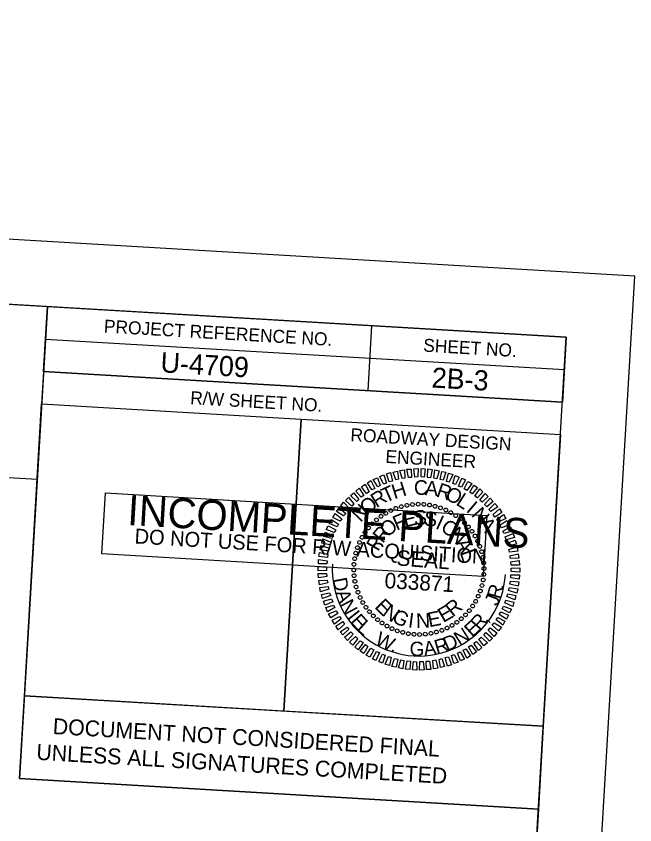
# Model space of a CAD drawing. Extents: x 2011701 to 2013463, y 444552 to 445750.
# Drawn here: x 2013225 to 2013463.2, y 445439.1 to 445750.4 of the extents above; entities that cross this region are included whole.
import ezdxf

# ---------------------------------------------------------------- set-up
doc = ezdxf.new("R2010")
doc.units = 0
for name, color, linetype in [('Old_Level_58', 7, 'Continuous'), ('Scratch_Level_0', 7, 'Continuous'), ('Sheet Clip Boundary CELL', 7, 'Continuous'), ('Sheet Data Field CELL', 7, 'Continuous'), ('Sheet Plan And Profile CELL', 7, 'Continuous'), ('Sheet Plot Border Outside CELL', 7, 'Continuous'), ('Sheet Professional Seal CELL', 7, 'Continuous'), ('Sheet Profile Grid Minor CELL', 7, 'Continuous'), ('Sheet Sticker Exception Certification CELL', 7, 'Continuous'), ('Sheet Sticker Incomplete CELL', 7, 'Continuous')]:
    doc.layers.add(name, color=color, linetype=linetype)

msp = doc.modelspace()

# ---------------------------------------------------------------- linework, layer by layer
at = {"layer": 'Old_Level_58'}
msp.add_lwpolyline([(2013037.32, 445650.4), (2013237.02, 445638.63), (2013233.1, 445572.05), (2013033.4, 445583.82)], close=True, dxfattribs=at)
at = {"layer": 'Scratch_Level_0'}
msp.add_arc((2013380.03, 445537.48), 33.36, 176.6264, 356.6264, dxfattribs=at)
at = {"layer": 'Sheet Clip Boundary CELL'}
msp.add_lwpolyline([(2011939.33, 445715.12), (2013237.02, 445638.63), (2013226.31, 445456.93), (2013426.02, 445445.16), (2013374.94, 444578.67), (2011877.54, 444666.94)], close=True, dxfattribs=at)
at = {"layer": 'Sheet Plan And Profile CELL'}
for p, q in [((2013361.85, 445631.22), (2013360.38, 445606.26)), ((2013236.29, 445626.1), (2013435.99, 445614.33)), ((2013235.55, 445613.62), (2013234.81, 445601.14)), ((2013235.55, 445613.62), (2013435.25, 445601.85)), ((2013334.69, 445595.25), (2013328.07, 445483))]:
    msp.add_line(p, q, dxfattribs=at)
for points in [[(2013436.73, 445626.85), (2011939.33, 445715.12), (2011877.54, 444666.94), (2013374.94, 444578.67)], [(2013237.02, 445638.63), (2013436.73, 445626.85), (2013435.25, 445601.85), (2013235.55, 445613.62)], [(2013234.81, 445601.14), (2013334.69, 445595.25), (2013328.07, 445482.95), (2013228.19, 445488.84)], [(2013334.69, 445595.25), (2013434.52, 445589.37), (2013427.9, 445477.06), (2013328.07, 445482.95)]]:
    msp.add_lwpolyline(points, close=True, dxfattribs=at)
at = {"layer": 'Sheet Plot Border Outside CELL'}
msp.add_lwpolyline([(2011701.37, 444652.28), (2013398.42, 444552.25), (2013463.16, 445650.34), (2011766.1, 445750.38)], close=True, dxfattribs=at)
at = {"layer": 'Sheet Professional Seal CELL'}
for p, q in [((2013369.19, 445560.11), (2013369.19, 445560.11)), ((2013371.2, 445561), (2013371.2, 445561)), ((2013373.24, 445561.68), (2013373.24, 445561.68)), ((2013375.38, 445562.15), (2013375.38, 445562.15)), ((2013377.59, 445562.42), (2013377.59, 445562.42)), ((2013379.76, 445562.59), (2013379.76, 445562.59)), ((2013381.96, 445562.51), (2013381.96, 445562.51)), ((2013384.15, 445562.24), (2013384.15, 445562.24)), ((2013386.27, 445561.76), (2013386.27, 445561.76)), ((2013388.34, 445561.19), (2013388.34, 445561.19)), ((2013390.4, 445560.36), (2013390.4, 445560.36)), ((2013363.67, 445556.53), (2013363.67, 445556.53)), ((2013365.41, 445557.93), (2013365.41, 445557.93)), ((2013367.23, 445559.08), (2013367.23, 445559.08)), ((2013392.34, 445559.35), (2013392.34, 445559.35)), ((2013394.23, 445558.24), (2013394.23, 445558.24)), ((2013395.95, 445556.88), (2013395.95, 445556.88)), ((2013360.63, 445553.4), (2013360.63, 445553.4)), ((2013362.09, 445555.07), (2013362.09, 445555.07)), ((2013397.62, 445555.43), (2013397.62, 445555.43)), ((2013399.08, 445553.84), (2013399.08, 445553.84)), ((2013359.28, 445551.68), (2013359.28, 445551.68)), ((2013400.48, 445552.11), (2013400.48, 445552.11)), ((2013401.62, 445550.29), (2013401.62, 445550.29)), ((2013357.15, 445547.85), (2013357.15, 445547.85)), ((2013358.17, 445549.79), (2013358.17, 445549.79)), ((2013402.66, 445548.32), (2013402.66, 445548.32)), ((2013356.33, 445545.79), (2013356.33, 445545.79)), ((2013403.54, 445546.32), (2013403.54, 445546.32)), ((2013404.22, 445544.27), (2013404.22, 445544.27)), ((2013355.28, 445541.6), (2013355.28, 445541.6)), ((2013355.76, 445543.72), (2013355.76, 445543.72)), ((2013404.7, 445542.14), (2013404.7, 445542.14)), ((2013355, 445539.41), (2013355, 445539.41)), ((2013404.97, 445539.92), (2013404.97, 445539.92)), ((2013405.14, 445537.76), (2013405.14, 445537.76)), ((2013354.92, 445537.21), (2013354.92, 445537.21)), ((2013355.1, 445535.05), (2013355.1, 445535.05)), ((2013380.03, 445537.48), (2013380.03, 445537.48)), ((2013405.06, 445535.56), (2013405.06, 445535.56)), ((2013355.36, 445532.83), (2013355.36, 445532.83)), ((2013404.78, 445533.37), (2013404.78, 445533.37)), ((2013355.84, 445530.7), (2013355.84, 445530.7)), ((2013356.52, 445528.65), (2013356.52, 445528.65)), ((2013403.73, 445529.18), (2013403.73, 445529.18)), ((2013404.31, 445531.25), (2013404.31, 445531.25)), ((2013357.4, 445526.65), (2013357.4, 445526.65)), ((2013402.91, 445527.12), (2013402.91, 445527.12)), ((2013358.44, 445524.68), (2013358.44, 445524.68)), ((2013359.59, 445522.86), (2013359.59, 445522.86)), ((2013400.78, 445523.29), (2013400.78, 445523.29)), ((2013401.9, 445525.18), (2013401.9, 445525.18)), ((2013360.99, 445521.13), (2013360.99, 445521.13)), ((2013362.45, 445519.54), (2013362.45, 445519.54)), ((2013397.98, 445519.9), (2013397.98, 445519.9)), ((2013399.43, 445521.57), (2013399.43, 445521.57)), ((2013364.11, 445518.09), (2013364.11, 445518.09)), ((2013365.84, 445516.73), (2013365.84, 445516.73)), ((2013394.65, 445517.04), (2013394.65, 445517.04)), ((2013396.39, 445518.44), (2013396.39, 445518.44)), ((2013367.72, 445515.62), (2013367.72, 445515.62)), ((2013369.67, 445514.61), (2013369.67, 445514.61)), ((2013371.72, 445513.78), (2013371.72, 445513.78)), ((2013373.79, 445513.21), (2013373.79, 445513.21)), ((2013384.69, 445512.82), (2013384.69, 445512.82)), ((2013386.82, 445513.29), (2013386.82, 445513.29)), ((2013388.86, 445513.97), (2013388.86, 445513.97)), ((2013390.87, 445514.86), (2013390.87, 445514.86)), ((2013392.83, 445515.89), (2013392.83, 445515.89)), ((2013375.92, 445512.73), (2013375.92, 445512.73)), ((2013378.11, 445512.45), (2013378.11, 445512.45)), ((2013380.3, 445512.38), (2013380.3, 445512.38)), ((2013382.47, 445512.55), (2013382.47, 445512.55))]:
    msp.add_line(p, q, dxfattribs=at)
for points in [[(2013371.14, 445571.87), (2013370.17, 445574.93), (2013371.74, 445575.29), (2013372.21, 445572.16)], [(2013373.57, 445572.38), (2013372.71, 445575.58), (2013374.43, 445575.83), (2013374.64, 445572.56)], [(2013376, 445572.78), (2013375.39, 445576.02), (2013377.05, 445576.08), (2013377.21, 445572.86)], [(2013378.42, 445572.94), (2013378.05, 445576.17), (2013379.76, 445576.27), (2013379.62, 445573.02)], [(2013380.93, 445573.04), (2013380.87, 445576.3), (2013382.51, 445576.16), (2013382.12, 445572.92)], [(2013383.32, 445572.85), (2013383.51, 445576.1), (2013385.15, 445575.95), (2013384.51, 445572.73)], [(2013385.81, 445572.56), (2013386.2, 445575.79), (2013387.83, 445575.39), (2013386.99, 445572.29)], [(2013388.18, 445572.02), (2013388.82, 445575.18), (2013390.45, 445574.84), (2013389.37, 445571.79)], [(2013364.17, 445569.22), (2013362.48, 445572.03), (2013364.08, 445572.73), (2013365.16, 445569.77)], [(2013366.39, 445570.29), (2013364.96, 445573.18), (2013366.54, 445573.79), (2013367.51, 445570.68)], [(2013368.65, 445571.21), (2013367.52, 445574.18), (2013369.05, 445574.7), (2013369.91, 445571.44)], [(2013390.69, 445571.32), (2013391.38, 445574.53), (2013393.05, 445574.03), (2013391.72, 445571)], [(2013393.05, 445570.53), (2013393.98, 445573.58), (2013395.5, 445572.99), (2013394.08, 445570.11)], [(2013395.24, 445569.5), (2013396.58, 445572.57), (2013397.94, 445571.89), (2013396.37, 445569.08)], [(2013359.92, 445566.72), (2013357.91, 445569.24), (2013359.32, 445570.21), (2013360.9, 445567.31)], [(2013361.9, 445568.1), (2013360.21, 445570.76), (2013361.56, 445571.63), (2013363.04, 445568.64)], [(2013397.43, 445568.41), (2013398.85, 445571.29), (2013400.36, 445570.5), (2013398.5, 445567.8)], [(2013399.66, 445567.13), (2013401.18, 445569.9), (2013402.62, 445568.96), (2013400.57, 445566.48)], [(2013356.08, 445563.64), (2013353.65, 445565.84), (2013354.97, 445566.91), (2013356.93, 445564.39)], [(2013357.83, 445565.29), (2013355.76, 445567.62), (2013357.03, 445568.74), (2013358.82, 445565.93)], [(2013401.53, 445565.67), (2013403.45, 445568.46), (2013404.68, 445567.34), (2013402.59, 445565.01)], [(2013403.49, 445564.05), (2013405.49, 445566.69), (2013406.73, 445565.51), (2013404.39, 445563.3)], [(2013352.61, 445560.04), (2013350.02, 445561.89), (2013351.05, 445563.29), (2013353.32, 445560.95)], [(2013354.22, 445561.85), (2013351.74, 445563.95), (2013352.91, 445565.18), (2013354.97, 445562.7)], [(2013405.29, 445562.39), (2013407.49, 445564.87), (2013408.62, 445563.6), (2013406.2, 445561.59)], [(2013406.99, 445560.54), (2013409.27, 445562.76), (2013410.4, 445561.49), (2013407.69, 445559.7)], [(2013351, 445558.13), (2013348.29, 445559.79), (2013349.37, 445561.13), (2013351.85, 445558.98)], [(2013408.63, 445558.64), (2013411.05, 445560.75), (2013412.02, 445559.34), (2013409.27, 445557.6)], [(2013348.54, 445553.82), (2013345.51, 445555.15), (2013346.35, 445556.65), (2013349.1, 445554.89)], [(2013349.67, 445556.05), (2013346.9, 445557.47), (2013347.74, 445558.97), (2013350.33, 445556.97)], [(2013410.01, 445556.6), (2013412.58, 445558.56), (2013413.44, 445557.05), (2013410.55, 445555.62)], [(2013347.41, 445551.68), (2013344.37, 445552.76), (2013345.11, 445554.27), (2013348.02, 445552.69)], [(2013411.19, 445554.48), (2013413.94, 445556.22), (2013414.8, 445554.67), (2013411.83, 445553.44)], [(2013412.35, 445552.21), (2013415.25, 445553.79), (2013415.81, 445552.2), (2013412.9, 445551.22)], [(2013346.52, 445549.33), (2013343.46, 445550.16), (2013343.91, 445551.79), (2013346.98, 445550.35)], [(2013413.23, 445550), (2013416.26, 445551.33), (2013416.81, 445549.69), (2013413.66, 445548.88)], [(2013345.73, 445546.97), (2013342.66, 445547.55), (2013343.11, 445549.23), (2013346.19, 445547.99)], [(2013413.99, 445547.6), (2013417.11, 445548.72), (2013417.57, 445547.14), (2013414.42, 445546.53)], [(2013344.79, 445542.07), (2013341.55, 445542.36), (2013341.75, 445544), (2013344.96, 445543.26)], [(2013345.18, 445544.45), (2013342, 445544.94), (2013342.3, 445546.62), (2013345.5, 445545.63)], [(2013414.64, 445545.16), (2013417.91, 445546.12), (2013418.11, 445544.46), (2013414.93, 445544.09)], [(2013344.59, 445539.57), (2013341.34, 445539.62), (2013341.44, 445541.31), (2013344.66, 445540.77)], [(2013415.1, 445542.73), (2013418.3, 445543.49), (2013418.5, 445541.78), (2013415.34, 445541.66)], [(2013415.41, 445540.31), (2013418.69, 445540.82), (2013418.74, 445539.11), (2013415.54, 445539.1)], [(2013344.5, 445537.08), (2013341.23, 445536.87), (2013341.23, 445538.57), (2013344.47, 445538.28)], [(2013415.57, 445537.89), (2013418.84, 445538.1), (2013418.84, 445536.4), (2013415.6, 445536.69)], [(2013344.65, 445534.66), (2013341.37, 445534.15), (2013341.32, 445535.86), (2013344.53, 445535.87)], [(2013415.47, 445535.4), (2013418.72, 445535.35), (2013418.62, 445533.66), (2013415.4, 445534.2)], [(2013344.96, 445532.24), (2013341.76, 445531.48), (2013341.56, 445533.19), (2013344.72, 445533.31)], [(2013415.27, 445532.9), (2013418.51, 445532.61), (2013418.31, 445530.97), (2013415.1, 445531.71)], [(2013345.42, 445529.81), (2013342.16, 445528.85), (2013341.96, 445530.51), (2013345.13, 445530.88)], [(2013346.08, 445527.37), (2013342.96, 445526.25), (2013342.5, 445527.83), (2013345.64, 445528.44)], [(2013414.88, 445530.52), (2013418.06, 445530.03), (2013417.76, 445528.35), (2013414.56, 445529.34)], [(2013346.84, 445524.97), (2013343.8, 445523.64), (2013343.25, 445525.28), (2013346.4, 445526.09)], [(2013413.54, 445525.64), (2013416.6, 445524.81), (2013416.15, 445523.18), (2013413.08, 445524.62)], [(2013414.33, 445528), (2013417.4, 445527.42), (2013416.95, 445525.74), (2013413.87, 445526.98)], [(2013347.71, 445522.76), (2013344.81, 445521.18), (2013344.25, 445522.76), (2013347.17, 445523.75)], [(2013412.65, 445523.29), (2013415.69, 445522.21), (2013414.95, 445520.7), (2013412.04, 445522.27)], [(2013348.88, 445520.49), (2013346.12, 445518.75), (2013345.26, 445520.3), (2013348.24, 445521.53)], [(2013350.05, 445518.37), (2013347.49, 445516.41), (2013346.62, 445517.92), (2013349.51, 445519.35)], [(2013411.53, 445521.15), (2013414.55, 445519.82), (2013413.71, 445518.32), (2013410.96, 445520.08)], [(2013351.44, 445516.33), (2013349.01, 445514.22), (2013348.04, 445515.63), (2013350.8, 445517.37)], [(2013409.07, 445516.84), (2013411.77, 445515.18), (2013410.69, 445513.84), (2013408.22, 445515.99)], [(2013410.39, 445518.92), (2013413.16, 445517.5), (2013412.32, 445516), (2013409.74, 445518)], [(2013353.08, 445514.43), (2013350.79, 445512.21), (2013349.67, 445513.48), (2013352.38, 445515.27)], [(2013354.77, 445512.58), (2013352.57, 445510.1), (2013351.45, 445511.37), (2013353.87, 445513.38)], [(2013405.84, 445513.12), (2013408.32, 445511.02), (2013407.15, 445509.79), (2013405.09, 445512.27)], [(2013407.45, 445514.93), (2013410.05, 445513.08), (2013409.01, 445511.68), (2013406.75, 445514.02)], [(2013356.58, 445510.92), (2013354.57, 445508.28), (2013353.34, 445509.46), (2013355.67, 445511.67)], [(2013358.54, 445509.3), (2013356.62, 445506.51), (2013355.38, 445507.63), (2013357.47, 445509.96)], [(2013403.98, 445511.33), (2013406.41, 445509.13), (2013405.09, 445508.06), (2013403.14, 445510.58)], [(2013360.4, 445507.84), (2013358.89, 445505.07), (2013357.44, 445506.01), (2013359.49, 445508.49)], [(2013362.63, 445506.56), (2013361.21, 445503.68), (2013359.7, 445504.47), (2013361.57, 445507.17)], [(2013398.16, 445506.86), (2013399.86, 445504.21), (2013398.5, 445503.34), (2013397.03, 445506.33)], [(2013400.15, 445508.25), (2013402.15, 445505.73), (2013400.74, 445504.76), (2013399.16, 445507.66)], [(2013402.23, 445509.68), (2013404.3, 445507.35), (2013403.03, 445506.23), (2013401.24, 445509.04)], [(2013364.82, 445505.47), (2013363.49, 445502.4), (2013362.13, 445503.08), (2013363.69, 445505.89)], [(2013367.01, 445504.44), (2013366.08, 445501.39), (2013364.57, 445501.98), (2013365.99, 445504.85)], [(2013369.37, 445503.65), (2013368.68, 445500.44), (2013367.01, 445500.94), (2013368.34, 445503.96)], [(2013391.42, 445503.76), (2013392.54, 445500.78), (2013391.01, 445500.27), (2013390.15, 445503.53)], [(2013393.67, 445504.68), (2013395.11, 445501.79), (2013393.52, 445501.18), (2013392.55, 445504.29)], [(2013395.89, 445505.75), (2013397.58, 445502.94), (2013395.99, 445502.23), (2013394.91, 445505.2)], [(2013371.89, 445502.95), (2013371.25, 445499.79), (2013369.62, 445500.13), (2013370.7, 445503.17)], [(2013374.26, 445502.41), (2013373.87, 445499.18), (2013372.24, 445499.58), (2013373.07, 445502.68)], [(2013376.74, 445502.12), (2013376.55, 445498.87), (2013374.91, 445499.02), (2013375.55, 445502.24)], [(2013379.14, 445501.93), (2013379.2, 445498.67), (2013377.55, 445498.81), (2013377.94, 445502.05)], [(2013381.65, 445502.03), (2013382.01, 445498.8), (2013380.3, 445498.7), (2013380.44, 445501.95)], [(2013384.06, 445502.19), (2013384.67, 445498.94), (2013383.02, 445498.89), (2013382.85, 445502.11)], [(2013386.49, 445502.59), (2013387.35, 445499.39), (2013385.63, 445499.14), (2013385.43, 445502.41)], [(2013388.92, 445503.1), (2013389.9, 445500.04), (2013388.32, 445499.68), (2013387.86, 445502.81)]]:
    msp.add_lwpolyline(points, close=True, dxfattribs=at)
for centre, major_axis in [((2013375.41, 445562.13), (-0.133, 0.708)), ((2013377.57, 445562.44), (-0.071, 0.717)), ((2013379.76, 445562.56), (-0.008, 0.72)), ((2013381.94, 445562.49), (0.055, 0.718)), ((2013384.12, 445562.23), (0.117, 0.71)), ((2013367.26, 445559.07), (-0.367, 0.62)), ((2013369.18, 445560.1), (-0.311, 0.649)), ((2013371.2, 445560.96), (-0.254, 0.674)), ((2013373.28, 445561.64), (-0.194, 0.693)), ((2013386.26, 445561.78), (0.179, 0.697)), ((2013388.35, 445561.14), (0.239, 0.679)), ((2013390.38, 445560.33), (0.297, 0.656)), ((2013392.33, 445559.34), (0.353, 0.627)), ((2013363.7, 445556.52), (-0.469, 0.546)), ((2013365.42, 445557.87), (-0.419, 0.585)), ((2013394.19, 445558.19), (0.407, 0.594)), ((2013395.94, 445556.87), (0.457, 0.557)), ((2013360.64, 445553.39), (-0.557, 0.457)), ((2013362.1, 445555.02), (-0.515, 0.504)), ((2013397.57, 445555.41), (0.504, 0.515)), ((2013399.07, 445553.82), (0.546, 0.469)), ((2013358.18, 445549.79), (-0.627, 0.353)), ((2013359.33, 445551.64), (-0.594, 0.407)), ((2013400.42, 445552.09), (0.585, 0.419)), ((2013401.61, 445550.26), (0.62, 0.367)), ((2013357.19, 445547.83), (-0.656, 0.297)), ((2013402.64, 445548.33), (0.649, 0.311)), ((2013403.5, 445546.32), (0.674, 0.254)), ((2013355.74, 445543.71), (-0.697, 0.179)), ((2013356.37, 445545.8), (-0.679, 0.239)), ((2013404.18, 445544.24), (0.693, 0.194)), ((2013355.29, 445541.57), (-0.71, 0.117)), ((2013404.68, 445542.11), (0.708, 0.133)), ((2013354.95, 445537.21), (-0.72, -0.008)), ((2013355.02, 445539.4), (-0.718, 0.055)), ((2013404.99, 445539.94), (0.717, 0.071)), ((2013405.11, 445537.76), (0.72, 0.008)), ((2013355.07, 445535.03), (-0.717, -0.071)), ((2013405.04, 445535.57), (0.718, -0.055)), ((2013355.38, 445532.86), (-0.708, -0.133)), ((2013355.88, 445530.73), (-0.693, -0.194)), ((2013404.33, 445531.26), (0.697, -0.179)), ((2013404.78, 445533.4), (0.71, -0.117)), ((2013356.56, 445528.65), (-0.674, -0.254)), ((2013403.69, 445529.17), (0.679, -0.239)), ((2013357.42, 445526.64), (-0.649, -0.311)), ((2013358.45, 445524.71), (-0.62, -0.367)), ((2013401.89, 445525.18), (0.627, -0.353)), ((2013402.88, 445527.13), (0.656, -0.297)), ((2013359.65, 445522.88), (-0.585, -0.419)), ((2013399.42, 445521.57), (0.557, -0.457)), ((2013400.73, 445523.33), (0.594, -0.407)), ((2013361, 445521.15), (-0.546, -0.469)), ((2013362.49, 445519.56), (-0.504, -0.515)), ((2013396.36, 445518.45), (0.469, -0.546)), ((2013397.96, 445519.95), (0.515, -0.504)), ((2013364.12, 445518.1), (-0.457, -0.557)), ((2013365.87, 445516.78), (-0.407, -0.594)), ((2013367.73, 445515.63), (-0.353, -0.627)), ((2013392.81, 445515.9), (0.367, -0.62)), ((2013394.64, 445517.1), (0.419, -0.585)), ((2013369.68, 445514.64), (-0.297, -0.656)), ((2013371.71, 445513.82), (-0.239, -0.679)), ((2013373.81, 445513.19), (-0.179, -0.697)), ((2013375.95, 445512.74), (-0.117, -0.71)), ((2013378.12, 445512.48), (-0.055, -0.718)), ((2013380.31, 445512.41), (0.008, -0.72)), ((2013382.49, 445512.53), (0.071, -0.717)), ((2013384.66, 445512.83), (0.133, -0.708)), ((2013386.79, 445513.33), (0.194, -0.693)), ((2013388.87, 445514.01), (0.254, -0.674)), ((2013390.88, 445514.87), (0.311, -0.649))]:
    msp.add_ellipse(centre, major_axis=major_axis, ratio=0.999708, dxfattribs=at)
at = {"layer": 'Sheet Sticker Exception Certification CELL'}
for p, q in [((2013226.31, 445456.93), (2013228.2, 445488.85)), ((2013228.2, 445488.85), (2013427.9, 445477.08)), ((2013427.9, 445477.06), (2013426.02, 445445.14)), ((2013426.02, 445445.16), (2013226.31, 445456.93))]:
    msp.add_line(p, q, dxfattribs=at)
at = {"layer": 'Sheet Sticker Incomplete CELL'}
msp.add_lwpolyline([(2013258.01, 445543.43), (2013259.39, 445566.89), (2013406.14, 445558.23), (2013404.75, 445534.78)], close=True, dxfattribs=at)

# ---------------------------------------------------------------- texts
at = {"layer": 'Sheet Data Field CELL'}
for s, p in [('U-4709', (2013280.41, 445613.33)), ('2B-3', (2013384.79, 445607.48))]:
    msp.add_text(s, height=7.75, rotation=356.6264, dxfattribs=at).set_placement(p)
at = {"layer": 'Sheet Plan And Profile CELL'}
for s, height, p in [('PROJECT REFERENCE NO.', 5.0001, (2013258.67, 445628.63)), ('SHEET NO.', 5, (2013381.6, 445621.29)), ('R/W SHEET NO.', 5.0001, (2013291.91, 445601.08)), ('ROADWAY DESIGN', 5.0001, (2013353.56, 445586.83)), ('ENGINEER', 5, (2013367.04, 445578.47))]:
    msp.add_text(s, height=height, rotation=356.6264, dxfattribs=at).set_placement(p)
at = {"layer": 'Sheet Professional Seal CELL'}
for s, height, rotation, p in [('T', 5.64, 24.4462, (2013367.21, 445562.98)), ('H', 5.64, 17.2459, (2013370.55, 445564.44)), ('C', 5.64, 2.8463, (2013378.26, 445565.99)), ('A', 5.64, 355.6467, (2013382.22, 445566.06)), ('R', 5.64, 341.2475, (2013386.4, 445565.61)), ('O', 5.64, 334.0476, (2013389.7, 445564.66)), ('R', 5.64, 31.6469, (2013363.69, 445560.99)), ('L', 5.64, 326.8473, (2013393.98, 445562.56)), ('N', 5.64, 46.0499, (2013357.59, 445555.34)), ('O', 5.64, 38.8482, (2013360.06, 445558.1)), ('I', 5.64, 319.6466, (2013397.88, 445559.92)), ('E', 5.64, 13.2375, (2013374.72, 445553.63)), ('S', 5.64, 3.882, (2013378.23, 445554.47)), ('S', 5.64, 354.5268, (2013381.82, 445554.31)), ('N', 5.64, 312.4453, (2013399.94, 445558.25)), ('O', 5.64, 41.3077, (2013367.97, 445549.57)), ('F', 5.64, 22.5935, (2013371.44, 445552.32)), ('I', 5.64, 335.816, (2013386.08, 445553.36)), ('A', 5.64, 305.2436, (2013402.71, 445555.13)), ('R', 5.64, 50.6661, (2013366.08, 445547.22)), ('O', 5.64, 326.4599, (2013388.03, 445552.54)), ('N', 5.64, 317.103, (2013391.26, 445550.35)), ('P', 5.64, 60.0253, (2013364.3, 445544.12)), ('A', 5.64, 298.3867, (2013393.95, 445547.58)), ('SEAL', 5.998, 355.6264, (2013371.26, 445539)), ('L', 5.64, 289.0273, (2013395.69, 445544.02)), ('E', 5.64, 314.9033, (2013362.74, 445522.83)), ('R', 5.64, 39.1078, (2013393.06, 445518.94)), ('N', 5.64, 324.2604, (2013365.58, 445519.96)), ('E', 5.64, 29.7505, (2013389.38, 445516.8)), ('G', 5.64, 333.6167, (2013369.24, 445517.49)), ('I', 5.64, 352.3276, (2013375.66, 445515.2)), ('N', 5.64, 1.6828, (2013379, 445514.86)), ('E', 5.64, 11.0382, (2013383.98, 445515.16))]:
    msp.add_text(s, height=height, rotation=rotation, dxfattribs=at).set_placement(p)
at = {"layer": 'Sheet Profile Grid Minor CELL'}
for s, height, rotation, p in [('033871', 5.998, 356.6264, (2013366.68, 445530.25)), ('D', 5.5, 280.8946, (2013346.77, 445533.79)), ('R', 5.5, 73.9805, (2013411.37, 445525.72)), ('A', 5.5, 290.0393, (2013347.78, 445528.55)), ('.', 5.5, 80.9069, (2013412.56, 445529.58)), ('N', 5.5, 298.2251, (2013349.38, 445524.05)), ('J', 5.5, 69.1119, (2013410.25, 445523.1)), ('I', 5.5, 308.1568, (2013352.15, 445518.97)), ('E', 5.5, 311.6772, (2013353.34, 445517.29)), ('R', 5.5, 49.0052, (2013403.47, 445513.59)), ('L', 5.5, 318.2602, (2013355.83, 445514.36)), ('E', 5.5, 42.4222, (2013400.57, 445511.06)), (',', 5.5, 55.9317, (2013406.18, 445516.59)), ('W', 5.5, 333.5156, (2013362.77, 445508.81)), ('N', 5.5, 32.4905, (2013395.71, 445507.91)), ('G', 5.5, 358.3019, (2013376.38, 445504.21)), ('A', 5.5, 8.2337, (2013382.17, 445504.08)), ('R', 5.5, 16.4194, (2013386.91, 445504.73)), ('D', 5.5, 23.3459, (2013390.81, 445505.8)), ('.', 5.5, 345.1217, (2013368.89, 445505.92))]:
    msp.add_text(s, height=height, rotation=rotation, dxfattribs=at).set_placement(p)
at = {"layer": 'Sheet Sticker Exception Certification CELL'}
for s, p in [('DOCUMENT NOT CONSIDERED FINAL', (2013238.97, 445474.11)), ('UNLESS ALL SIGNATURES COMPLETED', (2013232.65, 445464.21))]:
    msp.add_text(s, height=6.124, rotation=356.6264, dxfattribs=at).set_placement(p)
at = {"layer": 'Sheet Sticker Incomplete CELL'}
for s, height, p in [('INCOMPLETE PLANS', 11.52, (2013267.63, 445554.58)), ('DO NOT USE FOR R/W ACQUISITION', 5.76, (2013270.47, 445547.45))]:
    msp.add_text(s, height=height, rotation=356.6264, dxfattribs=at).set_placement(p)

doc.saveas('drawing.dxf')
